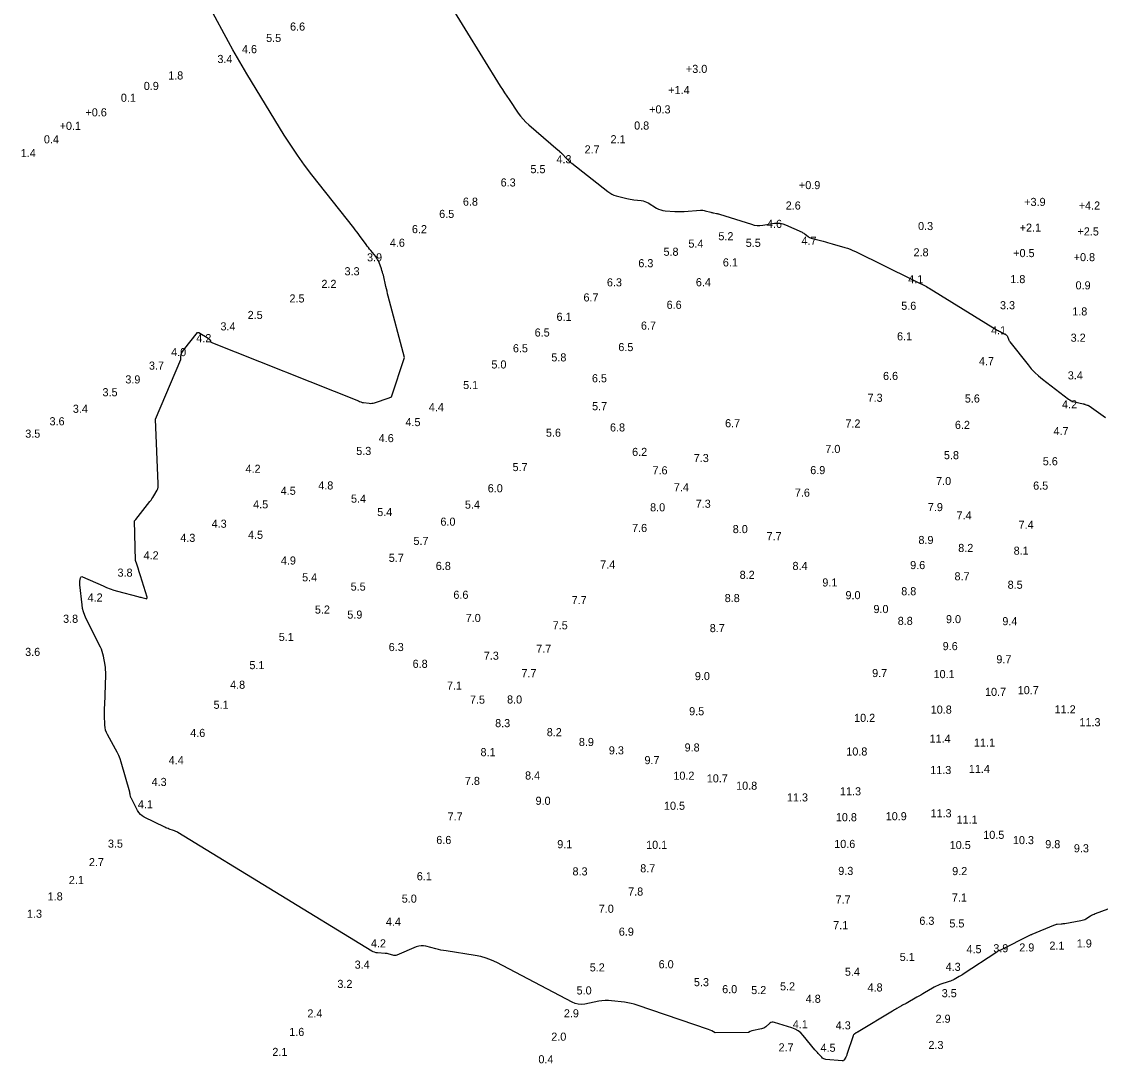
# Model space of a CAD drawing. Extents: x 837127 to 848654, y 3074248 to 3079868.
# Drawn here: x 845674.7 to 846091.6, y 3078230.4 to 3078632.8 of the extents above; entities that cross this region are included whole.
import ezdxf

# ---------------------------------------------------------------- set-up
doc = ezdxf.new("R2010")
doc.units = 0
doc.layers.add('V-HYDS-MAJR', color=7, linetype='Continuous')
doc.layers.add('V-HYDS-SOUN', color=7, linetype='Continuous')

msp = doc.modelspace()

# ---------------------------------------------------------------- linework, layer by layer
at = {"layer": 'V-HYDS-MAJR'}
for points in [[(845839.17, 3078641.15), (845859.66, 3078607.91), (845860.48, 3078606.58), (845861.32, 3078605.27), (845862.18, 3078603.96), (845863.05, 3078602.67), (845866.57, 3078597.51), (845867.49, 3078596.26), (845868.48, 3078595.07), (845869.56, 3078593.95), (845870.7, 3078592.9), (845882.03, 3078583.18), (845882.15, 3078583.08), (845882.26, 3078582.98), (845882.37, 3078582.88), (845882.48, 3078582.78), (845882.93, 3078582.37), (845883.04, 3078582.27), (845883.15, 3078582.16), (845883.26, 3078582.06), (845883.36, 3078581.95), (845885.56, 3078579.65), (845885.96, 3078579.24), (845886.38, 3078578.84), (845886.82, 3078578.46), (845887.27, 3078578.1), (845901.21, 3078567.18), (845901.97, 3078566.64), (845902.76, 3078566.2), (845903.6, 3078565.84), (845904.49, 3078565.56), (845908.52, 3078564.52), (845909.22, 3078564.35), (845909.91, 3078564.21), (845910.62, 3078564.09), (845911.32, 3078564), (845914.16, 3078563.67), (845914.85, 3078563.55), (845915.53, 3078563.37), (845916.18, 3078563.11), (845916.8, 3078562.78), (845920.09, 3078560.82), (845920.86, 3078560.42), (845921.66, 3078560.11), (845922.49, 3078559.91), (845923.35, 3078559.79), (845927.09, 3078559.52), (845928.01, 3078559.47), (845928.92, 3078559.46), (845929.84, 3078559.47), (845930.75, 3078559.52), (845937.08, 3078559.96), (845937.54, 3078559.97), (845937.99, 3078559.95), (845938.44, 3078559.88), (845938.89, 3078559.78), (845941, 3078559.2), (845941.28, 3078559.13), (845941.55, 3078559.06), (845941.83, 3078559), (845942.11, 3078558.94), (845943.22, 3078558.73), (845943.5, 3078558.68), (845943.77, 3078558.61), (845944.05, 3078558.54), (845944.32, 3078558.46), (845956.72, 3078554.52), (845957.81, 3078554.24), (845958.9, 3078554.09), (845960, 3078554.08), (845961.11, 3078554.19), (845965.58, 3078554.91), (845966.69, 3078555), (845967.77, 3078554.94), (845968.84, 3078554.72), (845969.88, 3078554.34), (845976.3, 3078551.45), (845976.62, 3078551.29), (845976.93, 3078551.11), (845977.23, 3078550.91), (845977.51, 3078550.69), (845978.61, 3078549.77), (845978.89, 3078549.55), (845979.2, 3078549.38), (845979.52, 3078549.24), (845979.86, 3078549.13), (845984.41, 3078547.97), (845985.28, 3078547.74), (845986.15, 3078547.51), (845987.02, 3078547.27), (845987.89, 3078547.02), (845992.75, 3078545.61), (845993.84, 3078545.27), (845994.91, 3078544.88), (845995.96, 3078544.44), (845996.99, 3078543.96), (846019.04, 3078533.08), (846019.57, 3078532.81), (846020.1, 3078532.55), (846020.64, 3078532.29), (846021.17, 3078532.04), (846023.32, 3078531.01), (846023.85, 3078530.74), (846024.38, 3078530.47), (846024.89, 3078530.18), (846025.4, 3078529.87), (846051.7, 3078513.7), (846052.06, 3078513.48), (846052.43, 3078513.27), (846052.79, 3078513.07), (846053.16, 3078512.88), (846054.88, 3078512), (846055.12, 3078511.85), (846055.32, 3078511.66), (846055.48, 3078511.44), (846055.6, 3078511.19), (846056.02, 3078510.1), (846056.13, 3078509.84), (846056.27, 3078509.58), (846056.42, 3078509.34), (846056.59, 3078509.1), (846063.59, 3078500.25), (846064.86, 3078498.74), (846066.22, 3078497.32), (846067.66, 3078495.99), (846069.18, 3078494.74), (846079.18, 3078487.04), (846079.71, 3078486.67), (846080.28, 3078486.36), (846080.87, 3078486.13), (846081.5, 3078485.95), (846084.95, 3078485.19), (846085.15, 3078485.15), (846085.34, 3078485.1), (846085.53, 3078485.04), (846085.72, 3078484.98), (846086.47, 3078484.73), (846086.66, 3078484.67), (846086.83, 3078484.58), (846087.01, 3078484.49), (846087.17, 3078484.38), (846093.5, 3078479.9)], [(846094.41, 3078290.05), (846089.56, 3078288.18), (846089.08, 3078287.99), (846088.62, 3078287.77), (846088.16, 3078287.53), (846087.71, 3078287.27), (846085.93, 3078286.19), (846085.48, 3078285.94), (846085.01, 3078285.74), (846084.53, 3078285.59), (846084.02, 3078285.48), (846077.77, 3078284.41), (846077.41, 3078284.36), (846077.05, 3078284.31), (846076.69, 3078284.26), (846076.33, 3078284.23), (846074.88, 3078284.1), (846074.52, 3078284.06), (846074.17, 3078283.99), (846073.83, 3078283.88), (846073.49, 3078283.76), (846065.12, 3078280.2), (846064.93, 3078280.12), (846064.73, 3078280.07), (846052.68, 3078274.08), (846052.64, 3078274.03), (846052.59, 3078274), (846052.53, 3078273.98), (846052.46, 3078273.97), (846052.19, 3078273.96), (846052.12, 3078273.96), (846052.06, 3078273.94), (846052, 3078273.91), (846051.95, 3078273.86), (846051.55, 3078273.47), (846051.47, 3078273.39), (846051.38, 3078273.31), (846051.29, 3078273.24), (846051.19, 3078273.17), (846038.9, 3078265.11), (846038.44, 3078264.81), (846037.97, 3078264.52), (846037.49, 3078264.24), (846037.02, 3078263.97), (846035.09, 3078262.9), (846034.6, 3078262.65), (846034.1, 3078262.42), (846033.59, 3078262.21), (846033.07, 3078262.03), (846029.54, 3078260.87), (846028.79, 3078260.6), (846028.06, 3078260.29), (846027.34, 3078259.94), (846026.64, 3078259.55), (846023.63, 3078257.73), (846022.89, 3078257.3), (846022.16, 3078256.86), (846021.42, 3078256.44), (846020.68, 3078256.01), (846016.47, 3078253.64), (846016.03, 3078253.39), (846015.58, 3078253.14), (846015.14, 3078252.88), (846014.7, 3078252.63), (846012.93, 3078251.62), (846012.49, 3078251.36), (846012.05, 3078251.11), (846011.61, 3078250.85), (846011.17, 3078250.59), (845997.96, 3078242.68), (845997.77, 3078242.56), (845997.58, 3078242.45), (845997.4, 3078242.33), (845997.22, 3078242.21), (845996.48, 3078241.74), (845996.31, 3078241.61), (845996.17, 3078241.46), (845996.06, 3078241.28), (845995.98, 3078241.09), (845993.64, 3078233.86), (845993.55, 3078233.59), (845993.44, 3078233.33), (845993.32, 3078233.08), (845993.18, 3078232.83), (845992.61, 3078231.85), (845992.45, 3078231.64), (845992.25, 3078231.5), (845992.02, 3078231.42), (845991.76, 3078231.41), (845985.53, 3078232.02), (845985.06, 3078232.11), (845984.63, 3078232.27), (845984.23, 3078232.52), (845983.88, 3078232.84), (845982.53, 3078234.27), (845982.19, 3078234.63), (845981.86, 3078234.99), (845981.54, 3078235.36), (845981.23, 3078235.74), (845976.68, 3078241.28), (845975.76, 3078242.25), (845974.74, 3078243.05), (845973.61, 3078243.7), (845972.38, 3078244.18), (845965.6, 3078246.29), (845965.13, 3078246.39), (845964.68, 3078246.36), (845964.26, 3078246.21), (845963.86, 3078245.93), (845962.32, 3078244.61), (845961.92, 3078244.3), (845961.49, 3078244.06), (845961.03, 3078243.87), (845960.55, 3078243.74), (845956.9, 3078243), (845956.19, 3078242.77), (845955.62, 3078242.39), (845942.65, 3078242.29), (845942.06, 3078242.67), (845941.45, 3078243.01), (845940.82, 3078243.3), (845940.17, 3078243.54), (845912.61, 3078252.94), (845911.41, 3078253.31), (845910.19, 3078253.63), (845908.95, 3078253.87), (845907.71, 3078254.06), (845902.69, 3078254.66), (845901.43, 3078254.76), (845900.19, 3078254.76), (845898.94, 3078254.66), (845897.7, 3078254.46), (845892.37, 3078253.39), (845891.08, 3078253.24), (845889.82, 3078253.31), (845888.6, 3078253.59), (845887.41, 3078254.1), (845858.32, 3078269.37), (845856.32, 3078270.32), (845854.26, 3078271.09), (845852.14, 3078271.7), (845849.97, 3078272.12), (845838.72, 3078273.87), (845837.74, 3078274.04), (845836.76, 3078274.23), (845835.79, 3078274.44), (845834.83, 3078274.69), (845830.98, 3078275.7), (845830.03, 3078275.88), (845829.08, 3078275.89), (845828.15, 3078275.75), (845827.23, 3078275.44), (845819.66, 3078272.28), (845819.31, 3078272.16), (845818.95, 3078272.11), (845818.59, 3078272.13), (845818.22, 3078272.21), (845816.76, 3078272.67), (845816.39, 3078272.78), (845816.02, 3078272.86), (845815.64, 3078272.92), (845815.26, 3078272.95), (845812.29, 3078273.13), (845811.68, 3078273.2), (845811.1, 3078273.35), (845810.53, 3078273.57), (845809.99, 3078273.85), (845735.06, 3078319.65), (845734.67, 3078319.87), (845734.27, 3078320.07), (845733.86, 3078320.25), (845733.44, 3078320.4), (845731.73, 3078320.97), (845731.31, 3078321.12), (845730.89, 3078321.28), (845730.48, 3078321.46), (845730.07, 3078321.65), (845722.09, 3078325.59), (845721.3, 3078326.06), (845720.61, 3078326.64), (845720.02, 3078327.31), (845719.54, 3078328.1), (845717.13, 3078332.73), (845717.04, 3078332.92), (845716.97, 3078333.11), (845716.9, 3078333.31), (845716.86, 3078333.51), (845716.69, 3078334.33), (845716.64, 3078334.54), (845716.6, 3078334.74), (845716.55, 3078334.95), (845716.49, 3078335.15), (845713.19, 3078346.77), (845712.77, 3078348.09), (845712.28, 3078349.38), (845711.71, 3078350.64), (845711.06, 3078351.87), (845707.91, 3078357.43), (845707.49, 3078358.3), (845707.18, 3078359.19), (845706.98, 3078360.12), (845706.91, 3078361.07), (845706.82, 3078364.97), (845706.8, 3078365.94), (845706.8, 3078366.91), (845706.81, 3078367.89), (845706.84, 3078368.86), (845707.24, 3078380.58), (845707.25, 3078381.49), (845707.2, 3078382.4), (845707.11, 3078383.3), (845706.97, 3078384.2), (845706.31, 3078387.79), (845706.11, 3078388.68), (845705.86, 3078389.55), (845705.54, 3078390.4), (845705.16, 3078391.22), (845699.69, 3078402.19), (845699.11, 3078403.47), (845698.66, 3078404.8), (845698.32, 3078406.15), (845698.11, 3078407.55), (845697.25, 3078415.34), (845697.23, 3078415.67), (845697.22, 3078416.01), (845697.24, 3078416.34), (845697.28, 3078416.67), (845697.49, 3078418), (845697.58, 3078418.27), (845697.73, 3078418.43), (845697.94, 3078418.47), (845698.21, 3078418.39), (845706.23, 3078414.84), (845707.59, 3078414.26), (845708.97, 3078413.74), (845710.38, 3078413.28), (845711.8, 3078412.87), (845719.63, 3078410.78), (845720.01, 3078410.68), (845720.39, 3078410.58), (845720.77, 3078410.48), (845721.15, 3078410.38), (845722.67, 3078409.97), (845722.99, 3078409.93), (845723.18, 3078410.01), (845723.25, 3078410.21), (845723.2, 3078410.52), (845720.67, 3078418.77), (845720.21, 3078420.26), (845719.73, 3078421.76), (845719.24, 3078423.25), (845718.74, 3078424.73), (845718.4, 3078439.98), (845718.89, 3078440.46), (845724.34, 3078447.47), (845724.73, 3078447.98), (845725.1, 3078448.51), (845725.45, 3078449.05), (845725.78, 3078449.6), (845727.07, 3078451.84), (845727.34, 3078452.41), (845727.49, 3078453), (845727.54, 3078453.6), (845727.47, 3078454.23), (845726.48, 3078479.26), (845736.27, 3078502.26), (845736.22, 3078503.52), (845736.56, 3078504.74), (845737.28, 3078505.91), (845742.7, 3078512.68), (845742.76, 3078512.74), (845742.82, 3078512.77), (845742.9, 3078512.78), (845742.97, 3078512.77), (845743.3, 3078512.68), (845743.38, 3078512.65), (845743.46, 3078512.62), (845743.53, 3078512.59), (845743.61, 3078512.54), (845746.48, 3078510.76), (845746.95, 3078510.42), (845747.34, 3078510.02), (845747.66, 3078509.55), (845747.9, 3078509.03), (845804.88, 3078486.39), (845805.35, 3078486.12), (845805.84, 3078485.92), (845806.34, 3078485.76), (845806.87, 3078485.67), (845809.03, 3078485.41), (845809.56, 3078485.37), (845810.09, 3078485.4), (845810.62, 3078485.48), (845811.14, 3078485.62), (845816.72, 3078487.46), (845817.65, 3078487.92), (845822.71, 3078503.13), (845816.41, 3078526.79), (845816.16, 3078527.71), (845815.93, 3078528.64), (845815.7, 3078529.57), (845815.49, 3078530.5), (845814.5, 3078534.82), (845814.34, 3078535.46), (845814.17, 3078536.09), (845813.97, 3078536.71), (845813.75, 3078537.33), (845812.85, 3078539.79), (845812.6, 3078540.39), (845812.3, 3078540.96), (845811.96, 3078541.51), (845811.57, 3078542.03), (845809.63, 3078544.38), (845809.17, 3078544.95), (845808.72, 3078545.52), (845808.28, 3078546.1), (845807.85, 3078546.68), (845805.35, 3078550.15), (845804.79, 3078550.92), (845804.22, 3078551.68), (845803.64, 3078552.44), (845803.05, 3078553.19), (845786.88, 3078573.69), (845784.04, 3078577.39), (845781.32, 3078581.18), (845778.72, 3078585.04), (845776.23, 3078588.99), (845761.78, 3078612.61), (845759.94, 3078615.68), (845758.14, 3078618.76), (845756.37, 3078621.87), (845754.65, 3078625), (845747.83, 3078637.58)]]:
    msp.add_lwpolyline(points, dxfattribs=at)

# ---------------------------------------------------------------- texts
at = {"layer": 'V-HYDS-SOUN'}
for s, p in [('6.6', (845778.46, 3078629.34)), ('5.5', (845769.2, 3078624.93)), ('3.4', (845750.38, 3078616.82)), ('4.6', (845759.87, 3078620.61)), ('+3.0 ', (845931.41, 3078612.99)), ('1.8', (845731.36, 3078610.45)), ('0.9', (845721.94, 3078606.41)), ('+1.4 ', (845924.59, 3078604.83)), ('0.1', (845713.08, 3078601.84)), ('+0.6 ', (845699.4, 3078596.21)), ('+0.3 ', (845917.21, 3078597.35)), ('+0.1 ', (845689.43, 3078591)), ('0.8', (845911.4, 3078591.12)), ('0.4', (845683.35, 3078585.79)), ('2.1', (845902.28, 3078585.82)), ('1.4', (845674.4, 3078580.49)), ('2.7', (845892.25, 3078581.9)), ('4.3', (845881.39, 3078578.1)), ('5.5', (845871.33, 3078574.27)), ('6.3', (845859.82, 3078569.13)), ('+0.9 ', (845975.08, 3078568.11)), ('6.8', (845845.24, 3078561.71)), ('2.6', (845969.96, 3078560.22)), ('+3.9 ', (846062.12, 3078561.61)), ('+4.2 ', (846083.19, 3078560.23)), ('6.5', (845836.07, 3078556.98)), ('6.2', (845825.54, 3078551.1)), ('4.6', (845962.71, 3078553.14)), ('0.3', (846021.1, 3078552.3)), ('+2.1 ', (846060.37, 3078551.68)), ('+2.5 ', (846082.7, 3078550.21)), ('4.6', (845817.01, 3078545.84)), ('5.2', (845943.95, 3078548.36)), ('5.5', (845954.52, 3078545.82)), ('4.7', (845976.06, 3078546.62)), ('5.8', (845922.74, 3078542.37)), ('5.4', (845932.37, 3078545.51)), ('2.8', (846019.35, 3078542.14)), ('+0.5 ', (846057.87, 3078541.85)), ('3.9', (845808.2, 3078540.21)), ('6.3', (845913.02, 3078537.94)), ('6.1', (845945.67, 3078538.25)), ('+0.8 ', (846081.24, 3078540.29)), ('3.3', (845799.51, 3078534.83)), ('2.2', (845790.58, 3078529.95)), ('6.3', (845900.88, 3078530.55)), ('6.4', (845935.25, 3078530.6)), ('4.1', (846017.29, 3078531.75)), ('1.8', (846056.74, 3078531.8)), ('0.9', (846081.96, 3078529.39)), ('2.5', (845778.23, 3078524.33)), ('6.7', (845891.82, 3078524.72)), ('6.6', (845923.95, 3078521.88)), ('5.6', (846014.6, 3078521.5)), ('3.3', (846052.76, 3078521.71)), ('2.5', (845762.07, 3078517.95)), ('6.1', (845881.41, 3078517.24)), ('1.8', (846080.68, 3078519.32)), ('3.4', (845751.56, 3078513.55)), ('6.7', (845914.03, 3078513.84)), ('4.2', (845742.23, 3078509)), ('6.5', (845872.96, 3078511.18)), ('6.1', (846012.97, 3078509.7)), ('4.1', (846049.32, 3078512.05)), ('3.2', (846080.05, 3078509.17)), ('6.5', (845864.56, 3078505.09)), ('6.5', (845905.29, 3078505.55)), ('4.0', (845732.51, 3078503.61)), ('5.8', (845879.41, 3078501.57)), ('4.7', (846044.63, 3078500.1)), ('3.7', (845723.93, 3078498.39)), ('5.0', (845856.25, 3078498.84)), ('3.9', (845714.81, 3078493.06)), ('6.5', (845895.09, 3078493.51)), ('6.6', (846007.56, 3078494.39)), ('3.4', (846078.96, 3078494.62)), ('3.5', (845706, 3078488.11)), ('5.1', (845845.32, 3078490.89)), ('7.3', (846001.59, 3078485.97)), ('5.6', (846039.17, 3078485.69)), ('4.2', (846076.74, 3078483.44)), ('3.4', (845694.54, 3078481.72)), ('4.4', (845832.08, 3078482.35)), ('5.7', (845895.15, 3078482.73)), ('3.6', (845685.53, 3078476.89)), ('4.5', (845823.03, 3078476.58)), ('6.7', (845946.54, 3078476.14)), ('7.2', (845993.03, 3078476.03)), ('6.2', (846035.34, 3078475.49)), ('3.5', (845676.14, 3078472.11)), ('5.6', (845877.32, 3078472.49)), ('6.8', (845902.07, 3078474.52)), ('4.7', (846073.43, 3078473.12)), ('4.6', (845812.71, 3078470.39)), ('5.3', (845804.02, 3078465.44)), ('6.2', (845910.63, 3078465.06)), ('7.3', (845934.43, 3078462.7)), ('7.0', (845985.27, 3078466.21)), ('5.8', (846031.1, 3078463.8)), ('4.2', (845761.24, 3078458.54)), ('5.7', (845864.42, 3078459.21)), ('5.6', (846069.29, 3078461.45)), ('7.6', (845918.5, 3078457.95)), ('6.9', (845979.44, 3078458.03)), ('4.5', (845774.85, 3078450.06)), ('4.8', (845789.35, 3078452.11)), ('6.0', (845854.83, 3078451.02)), ('7.4', (845926.74, 3078451.4)), ('7.0', (846028.07, 3078453.82)), ('6.5', (846065.57, 3078452.04)), ('5.4', (845802, 3078447.01)), ('7.6', (845973.5, 3078449.32)), ('4.5', (845764.19, 3078444.81)), ('5.4', (845812.12, 3078441.84)), ('5.4', (845846.01, 3078444.7)), ('8.0', (845917.58, 3078443.66)), ('7.3', (845935.19, 3078445.05)), ('7.9', (846024.88, 3078443.74)), ('6.0', (845836.55, 3078438.12)), ('7.4', (846035.97, 3078440.55)), ('4.3', (845748.15, 3078437.33)), ('7.6', (845910.61, 3078435.68)), ('8.0', (845949.5, 3078435.25)), ('7.4', (846059.95, 3078436.94)), ('4.3', (845736.04, 3078431.87)), ('4.5', (845762.21, 3078433.04)), ('5.7', (845826.14, 3078430.69)), ('7.7', (845962.57, 3078432.52)), ('8.9', (846021.25, 3078431.04)), ('4.2', (845721.86, 3078425.1)), ('8.2', (846036.62, 3078427.97)), ('8.1', (846058.03, 3078426.92)), ('4.9', (845774.91, 3078423.12)), ('5.7', (845816.6, 3078424.15)), ('6.8', (845834.77, 3078421.02)), ('7.4', (845898.28, 3078421.56)), ('8.4', (845972.59, 3078421.03)), ('9.6', (846018.05, 3078421.36)), ('3.8', (845711.79, 3078418.43)), ('5.4', (845783.11, 3078416.62)), ('8.2', (845952.17, 3078417.58)), ('8.7', (846035.18, 3078417.02)), ('5.5', (845801.87, 3078413.05)), ('9.1', (845984.12, 3078414.65)), ('8.5', (846055.71, 3078413.76)), ('4.2', (845700.22, 3078408.84)), ('6.6', (845841.56, 3078409.88)), ('8.8', (845946.39, 3078408.62)), ('9.0', (845993.06, 3078409.74)), ('8.8', (846014.6, 3078411.26)), ('5.2', (845788.05, 3078404.17)), ('7.7', (845887.25, 3078407.83)), ('9.0', (846003.87, 3078404.37)), ('3.8', (845690.76, 3078400.61)), ('5.9', (845800.58, 3078402.23)), ('7.0', (845846.32, 3078400.92)), ('9.0', (846031.89, 3078400.48)), ('7.5', (845879.93, 3078398.08)), ('8.7', (845940.62, 3078397.01)), ('8.8', (846013.24, 3078399.8)), ('9.4', (846053.67, 3078399.69)), ('5.1', (845774.09, 3078393.58)), ('3.6', (845676.1, 3078387.83)), ('6.3', (845816.57, 3078389.7)), ('7.7', (845873.58, 3078389.05)), ('9.6', (846030.62, 3078390.06)), ('6.8', (845825.81, 3078383.22)), ('7.3', (845853.32, 3078386.35)), ('9.7', (846051.35, 3078384.98)), ('5.1', (845762.75, 3078382.72)), ('7.7', (845867.86, 3078379.62)), ('9.7', (846003.36, 3078379.65)), ('10.1 ', (846027.09, 3078379.24)), ('4.8', (845755.29, 3078375.13)), ('9.0', (845934.86, 3078378.49)), ('7.1', (845839.09, 3078374.82)), ('10.7 ', (846046.97, 3078372.38)), ('10.7 ', (846059.61, 3078373.05)), ('5.1', (845748.89, 3078367.41)), ('7.5', (845847.96, 3078369.38)), ('8.0', (845862.3, 3078369.45)), ('9.5', (845932.65, 3078364.91)), ('10.8 ', (846025.99, 3078365.54)), ('11.2 ', (846073.87, 3078365.64)), ('8.3', (845857.7, 3078360.31)), ('10.2 ', (845996.39, 3078362.35)), ('11.3 ', (846083.46, 3078360.67)), ('4.6', (845739.88, 3078356.53)), ('8.2', (845877.64, 3078356.83)), ('11.4 ', (846025.53, 3078354.31)), ('8.9', (845890.04, 3078353.03)), ('9.8', (845930.9, 3078350.92)), ('11.1 ', (846042.71, 3078352.78)), ('4.4', (845731.58, 3078346)), ('8.1', (845852.04, 3078349.1)), ('9.3', (845901.63, 3078349.8)), ('9.7', (845915.39, 3078346.03)), ('10.8 ', (845993.37, 3078349.36)), ('11.3 ', (846025.8, 3078342.2)), ('11.4 ', (846040.71, 3078342.62)), ('4.3', (845724.96, 3078337.6)), ('7.8', (845846, 3078337.99)), ('8.4', (845869.26, 3078340.09)), ('10.2 ', (845926.56, 3078340.01)), ('10.7 ', (845939.47, 3078338.98)), ('10.8 ', (845950.81, 3078336.14)), ('11.3 ', (845990.94, 3078333.99)), ('9.0', (845873.31, 3078330.32)), ('11.3 ', (845970.44, 3078331.62)), ('4.1', (845719.65, 3078328.96)), ('10.5 ', (845922.93, 3078328.4)), ('11.3 ', (846025.91, 3078325.49)), ('7.7', (845839.33, 3078324.27)), ('10.8 ', (845989.33, 3078323.98)), ('10.9 ', (846008.6, 3078324.36)), ('11.1 ', (846035.96, 3078323.07)), ('10.5 ', (846046.29, 3078317.16)), ('3.5', (845708.08, 3078313.76)), ('6.6', (845834.95, 3078315.18)), ('9.1', (845881.69, 3078313.56)), ('10.1 ', (845916.03, 3078313.31)), ('10.6 ', (845988.71, 3078313.65)), ('10.5 ', (846033.33, 3078313.23)), ('10.3 ', (846057.75, 3078315.13)), ('9.8', (846070.24, 3078313.56)), ('9.3', (846081.3, 3078311.97)), ('2.7', (845700.73, 3078306.63)), ('8.7', (845913.76, 3078304.25)), ('6.1', (845827.42, 3078301.17)), ('8.3', (845887.59, 3078303.05)), ('9.3', (845990.27, 3078303.23)), ('9.2', (846034.28, 3078303.17)), ('2.1', (845692.98, 3078299.72)), ('1.8', (845684.8, 3078293.39)), ('5.0', (845821.61, 3078292.53)), ('7.8', (845909.09, 3078295.27)), ('7.7', (845989.23, 3078292.19)), ('7.1', (846034.17, 3078292.96)), ('7.0', (845897.73, 3078288.62)), ('1.3', (845676.81, 3078286.69)), ('4.4', (845815.48, 3078283.61)), ('6.3', (846021.6, 3078283.97)), ('6.9', (845905.48, 3078279.77)), ('7.1', (845988.29, 3078282.26)), ('5.5', (846033.2, 3078282.95)), ('4.2', (845809.7, 3078275.26)), ('1.9', (846082.43, 3078275.22)), ('4.5', (846039.82, 3078273.01)), ('3.9', (846050.17, 3078273.36)), ('2.9', (846060.2, 3078273.68)), ('2.1', (846071.85, 3078274.37)), ('3.4', (845803.41, 3078267.04)), ('6.0', (845920.86, 3078267.19)), ('5.1', (846014.01, 3078270)), ('5.2', (845894.25, 3078265.97)), ('5.4', (845992.83, 3078264.3)), ('4.3', (846031.75, 3078266.19)), ('3.2', (845796.74, 3078259.59)), ('5.3', (845934.5, 3078260.27)), ('5.2', (845967.77, 3078258.65)), ('4.8', (846001.58, 3078258.22)), ('5.0', (845889.17, 3078257.07)), ('6.0', (845945.41, 3078257.56)), ('5.2', (845956.63, 3078257.22)), ('3.5', (846030.24, 3078256)), ('4.8', (845977.69, 3078253.85)), ('2.4', (845785.16, 3078248.19)), ('2.9', (845884.25, 3078248.24)), ('2.9', (846027.85, 3078246.15)), ('4.1', (845972.7, 3078244.01)), ('4.3', (845989.28, 3078243.59)), ('1.6', (845778.14, 3078241.05)), ('2.0', (845879.38, 3078239.21)), ('2.1', (845771.61, 3078233.33)), ('2.7', (845967.2, 3078235.09)), ('4.5', (845983.41, 3078234.94)), ('2.3', (846025.1, 3078236)), ('0.4', (845874.41, 3078230.49))]:
    msp.add_text(s, height=3.125, dxfattribs=at).set_placement(p)

doc.saveas('drawing.dxf')
